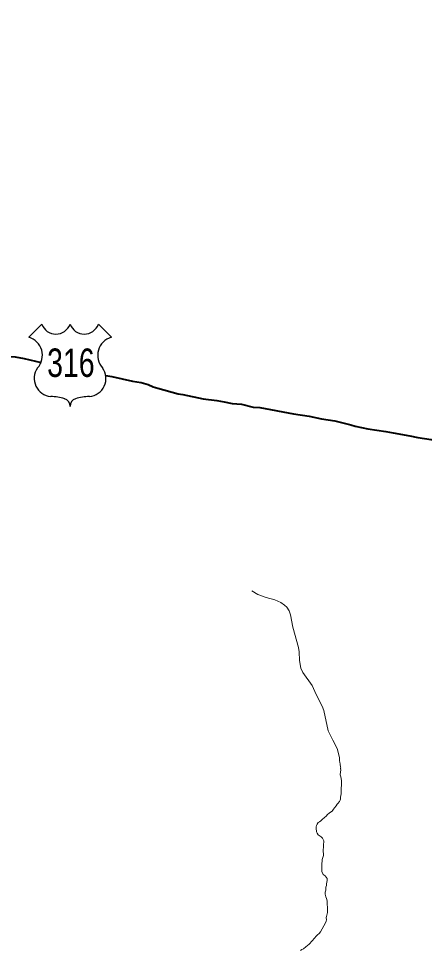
# Model space of a CAD drawing. Extents: x -1643653 to 4543381, y 1624270 to 13878484.
# Drawn here: x 613171 to 614173, y 8910770 to 8913066 of the extents above; entities that cross this region are included whole.
import ezdxf
from ezdxf.enums import TextEntityAlignment as Align

# ---------------------------------------------------------------- set-up
doc = ezdxf.new("R2010")
doc.units = 0
doc.header["$LTSCALE"] = 200
doc.layers.add('1', color=7, linetype='Continuous', lineweight=13)
doc.layers.add('6', color=7, linetype='Continuous', lineweight=13)

msp = doc.modelspace()

# ---------------------------------------------------------------- linework, layer by layer
at = {"layer": '1', "lineweight": 25}
msp.add_spline([(814781, 9009175.5), (814787.2, 9009173.4), (814796.9, 9009173.4), (814799.4, 9009172.4), (814805.1, 9009174.5), (814805.6, 9009176.5), (814811.7, 9009179.5), (814811.7, 9009179.5), (814801.5, 9009181), (814790.7, 9009181.5), (814784.1, 9009183.1), (814777.4, 9009185.1), (814778.4, 9009175.5)], degree=3, dxfattribs=at)
at = {"layer": '6', "lineweight": 25}
for p, q in [((613196.5, 8912280.5), (613228.5, 8912312.5)), ((613368.3, 8912312.5), (613400.3, 8912280.5))]:
    msp.add_line(p, q, dxfattribs=at)
at = {"layer": '6', "lineweight": 40}
for points in [[(613028.9, 8912249.9), (613104.3, 8912237.7), (613134.5, 8912234.3), (613163.2, 8912232.2), (613185.3, 8912228.2), (613226.8, 8912218.5)], [(613386.4, 8912186.2), (613401.2, 8912183.6), (613452.1, 8912172.7), (613474.2, 8912168.8), (613491.2, 8912163.9), (613503.7, 8912158.5), (613514.7, 8912154.8), (613564.8, 8912141), (613576.6, 8912139.3), (613626.7, 8912128.5), (613660.6, 8912124.5), (613678.3, 8912121.5), (613698.2, 8912117), (613721.1, 8912115.6), (613750.5, 8912108.4), (613766.3, 8912107.4), (613849.7, 8912091.9), (613888.1, 8912085.9), (613919, 8912079.5), (613951.5, 8912074.8), (613991.2, 8912065.2), (614002.3, 8912061.8), (614033.2, 8912054.9), (614077.8, 8912048.2), (614095.5, 8912045.1)], [(614095.5, 8912045.1), (614137.1, 8912037.7), (614156.6, 8912033.3), (614189.2, 8912028.5), (614215.5, 8912021.7), (614263.5, 8912005.4), (614314.9, 8911983.3), (614359.3, 8911958.1), (614413.5, 8911919.6), (614418.7, 8911918.6), (614421.7, 8911917.2), (614435.2, 8911906.1)]]:
    msp.add_lwpolyline(points, dxfattribs=at)
at = {"layer": '6'}
for points in [[(613746.6, 8911655.6), (613761.8, 8911647), (613782.4, 8911639.6), (613803.8, 8911633.7), (613818.3, 8911626.8), (613827.9, 8911620.8), (613832.9, 8911615.2), (613838.7, 8911606.9), (613842.3, 8911596.7), (613848.4, 8911566.1), (613862.4, 8911516.5), (613864.1, 8911505.6), (613864.4, 8911484.4), (613867.7, 8911465.5), (613872.8, 8911454.6), (613895.5, 8911422.3), (613905.6, 8911400.5), (613920.2, 8911371.9), (613924.2, 8911361), (613935.1, 8911310.7), (613946.5, 8911288.1), (613957.4, 8911267.5), (613963, 8911245.3)], [(613963, 8911245.3), (613963.4, 8911239.5), (613963.5, 8911237), (613964, 8911233.7), (613964.6, 8911229.1), (613965.9, 8911221.6), (613966.2, 8911220), (613966.3, 8911218.8), (613966.4, 8911218.5)], [(613966, 8911218.5), (613966.2, 8911213.3), (613966.1, 8911210.4), (613965.8, 8911207), (613965.3, 8911205.2), (613964.9, 8911202.2), (613965.7, 8911199.6), (613966.6, 8911197.7), (613967.8, 8911188.8), (613968.6, 8911182.6), (613968.1, 8911177), (613967.4, 8911169.7), (613967.3, 8911166.2), (613967.7, 8911163.2), (613967.1, 8911156.4), (613966.2, 8911150.8), (613965.8, 8911148.1), (613965.7, 8911142.8), (613964.8, 8911139.7), (613963.2, 8911136.5), (613959.5, 8911132.2), (613957.2, 8911129.9), (613954.8, 8911125.9), (613951.1, 8911121.5), (613948.5, 8911117.8), (613945.3, 8911113.3), (613943.9, 8911111.8), (613937.8, 8911108.3), (613933.6, 8911104.8), (613930.1, 8911100.6), (613926.5, 8911097.3), (613920.7, 8911092.4), (613917, 8911089.5), (613913.8, 8911087), (613911, 8911084.6), (613908.2, 8911080.6), (613906.3, 8911077.3), (613905.5, 8911074), (613905.7, 8911070.7)], [(613905.7, 8911070.7), (613906.7, 8911061.6), (613907.9, 8911058.6), (613910.9, 8911054.8), (613912.8, 8911052.8), (613917.7, 8911049.7), (613921.4, 8911046.2), (613922.5, 8911044.6), (613923.9, 8911041.5), (613924.7, 8911039.5), (613924.8, 8911036.7), (613923.9, 8911031.6), (613923.4, 8911026.2), (613923, 8911016), (613923.2, 8911011.7), (613923.7, 8911009.6)], [(613923.7, 8911009.6), (613923.4, 8911004.1), (613922.3, 8910999.1), (613921.6, 8910995.9), (613920.6, 8910993.5), (613920.2, 8910990.8), (613919.6, 8910983.3), (613919.7, 8910972.5), (613919.7, 8910965.9), (613920, 8910963.9), (613922, 8910958.4), (613923, 8910957), (613925.6, 8910955.1), (613927.6, 8910954), (613928.3, 8910953.5)], [(613928.3, 8910953.5), (613933.1, 8910947.2), (613933.2, 8910944.8), (613932.9, 8910941.7), (613931.1, 8910934), (613930.9, 8910929.6), (613929.9, 8910925.9), (613929.5, 8910923.4), (613929.8, 8910920.8), (613929.5, 8910918.5), (613927.9, 8910913.2), (613927.6, 8910910.2), (613927.8, 8910908.3), (613928.8, 8910904.8), (613929.5, 8910901.6), (613931.4, 8910897.8), (613932.2, 8910895.3), (613933, 8910891.4), (613933.2, 8910886.4), (613933.6, 8910872.7), (613934, 8910868.4), (613933.5, 8910863.2), (613930.9, 8910853.3), (613930.7, 8910851.1), (613931.3, 8910845.2), (613930.7, 8910841.7), (613929, 8910838), (613924.9, 8910830.6), (613920.9, 8910822.8), (613916, 8910815.5), (613913, 8910811.6), (613909, 8910808), (613905.3, 8910805), (613901.6, 8910800.4), (613896.1, 8910793.5), (613888.2, 8910785.5), (613880.1, 8910779), (613874.6, 8910774.1), (613870.3, 8910772.2), (613866.8, 8910770)]]:
    msp.add_lwpolyline(points, dxfattribs=at)
at = {"layer": '6', "lineweight": 25}
for centre, radius, start, end in [((613263.4, 8912325.9), 37.4, 200.9593, 339.0407), ((613333.4, 8912325.9), 37.4, 200.9593, 339.0407), ((613184.1, 8912236.1), 46.1, 317.5721, 74.3689), ((613412.7, 8912236.1), 46.1, 105.6277, 222.4279), ((613254.8, 8912179.1), 44.9, 144.7373, 264.6578), ((613342, 8912179.1), 44.9, 275.3422, 35.2627), ((613250.4, 8912016.4), 118, 72.8937, 89.9006), ((613279.5, 8912111.1), 18.9, 357.6934, 72.9296), ((613317.3, 8912111.1), 18.9, 107.0704, 182.3065), ((613346.4, 8912016.4), 118, 90.0994, 107.1063)]:
    msp.add_arc(centre, radius, start, end, dxfattribs=at)

# ---------------------------------------------------------------- texts
at = {"layer": '6', "width": 0.75}
msp.add_text('316', height=70, dxfattribs=at).set_placement((613300.4, 8912182.9), align=Align.CENTER)

doc.saveas('drawing.dxf')
